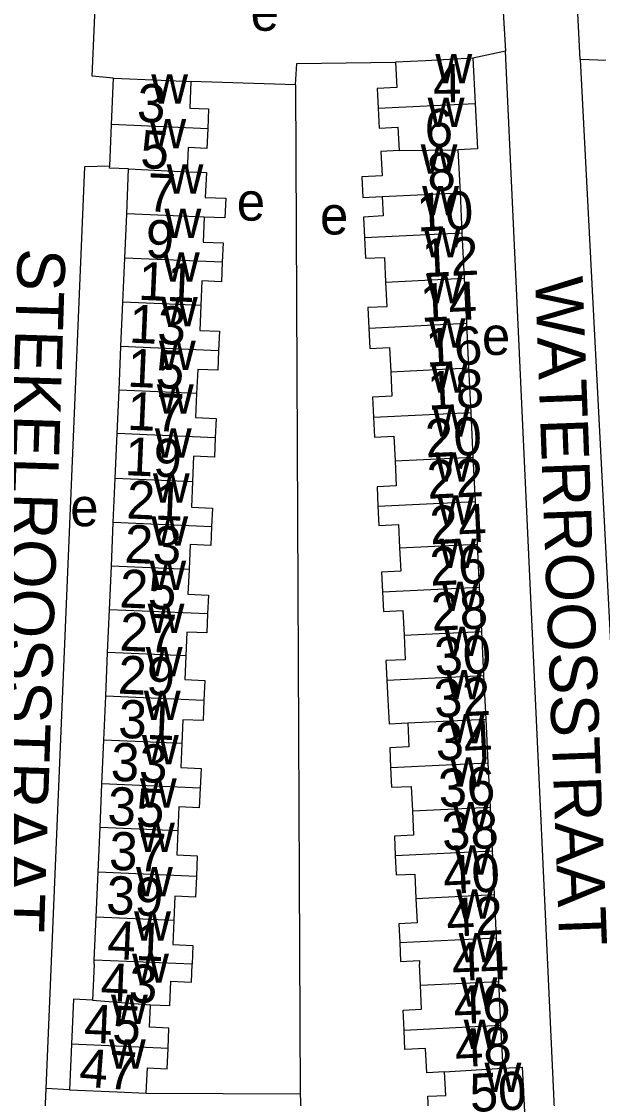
# Model space of a CAD drawing. Extents: x 161258 to 163262, y 380749 to 382054.
# Drawn here: x 162343 to 162403.5, y 380985.9 to 381098.8 of the extents above; entities that cross this region are included whole.
import ezdxf

# ---------------------------------------------------------------- set-up
doc = ezdxf.new("R2010")
doc.units = 0
for name, color, linetype in [('BLT_Basislijn', 7, 'Continuous'), ('BLT_Bebouwing', 7, 'Continuous'), ('BLT_Centroide', 7, 'Continuous'), ('BLT_Huisnummer', 7, 'Continuous'), ('BLT_Huisnummer_ tussenligend', 7, 'Continuous'), ('BLT_Onderverdeling_panden', 7, 'Continuous'), ('BLT_Straatnaam', 7, 'Continuous')]:
    doc.layers.add(name, color=color, linetype=linetype)

msp = doc.modelspace()

# ---------------------------------------------------------------- linework, layer by layer
at = {"layer": 'BLT_Basislijn'}
for p, q in [((162393.75, 381095.73), (162390.32, 381094.99)), ((162399.1, 380980.19), (162393.75, 381095.73)), ((162404.35, 381094.76), (162401.58, 381094.88)), ((162371.7, 381092.21), (162360.74, 381092.54)), ((162371.7, 381092.21), (162372.2, 380986.41)), ((162348.01, 380986.84), (162345.51, 380986.99)), ((162356.06, 380986.49), (162372.2, 380986.41))]:
    msp.add_line(p, q, dxfattribs=at)
for points in [[(162401.58, 381094.88), (162400.52, 381115.65), (162445.14, 381123.93), (162447.27, 381105.8), (162447.33, 381105.24)], [(162352.63, 381092.9), (162350.38, 381093.13), (162351.31, 381113.86), (162392.57, 381115.24), (162393.75, 381095.73)], [(162371.7, 381092.21), (162371.85, 381094.43), (162382.21, 381094.59)], [(162401.58, 381094.88), (162407.53, 380979.88), (162407.53, 380979.65)], [(162352.23, 381083.67), (162349.58, 381083.6), (162345.51, 380986.99)], [(162345.51, 380986.99), (162344.65, 380966.65), (162398.15, 380960.51), (162398.46, 380960.83), (162399.56, 380970.74), (162399.1, 380980.19)], [(162372.2, 380986.41), (162372.39, 380982.25), (162385.46, 380979.84), (162387.83, 380979.4)]]:
    msp.add_lwpolyline(points, dxfattribs=at)
at = {"layer": 'BLT_Bebouwing'}
for p, q in [((162390.32, 381094.99), (162390.55, 381090.26)), ((162352.42, 381088.05), (162352.63, 381092.9)), ((162390.55, 381090.26), (162390.79, 381085.49)), ((162352.23, 381083.67), (162352.42, 381088.05)), ((162390.79, 381085.49), (162388.75, 381085.39)), ((162388.75, 381085.39), (162388.97, 381080.89)), ((162354.01, 381078.7), (162354.21, 381083.39)), ((162388.97, 381080.89), (162389.17, 381076.69)), ((162353.81, 381074.04), (162354.01, 381078.7)), ((162389.17, 381076.69), (162389.4, 381071.93)), ((162353.61, 381069.41), (162353.81, 381074.04)), ((162389.4, 381071.93), (162389.64, 381067.21)), ((162353.4, 381064.77), (162353.61, 381069.41)), ((162389.64, 381067.21), (162389.86, 381062.52)), ((162353.21, 381060.2), (162353.4, 381064.77)), ((162389.86, 381062.52), (162390.09, 381057.87)), ((162353.01, 381055.65), (162353.21, 381060.2)), ((162390.09, 381057.87), (162390.32, 381053.17)), ((162352.81, 381050.95), (162353.01, 381055.65)), ((162390.32, 381053.17), (162390.54, 381048.53)), ((162352.6, 381046.32), (162352.81, 381050.95)), ((162390.54, 381048.53), (162390.76, 381044.05)), ((162352.41, 381041.75), (162352.6, 381046.32)), ((162390.76, 381044.05), (162390.98, 381039.55)), ((162352.21, 381037.18), (162352.41, 381041.75)), ((162390.98, 381039.55), (162391.21, 381034.91)), ((162352.01, 381032.7), (162352.21, 381037.18)), ((162391.21, 381034.91), (162391.43, 381030.28)), ((162351.81, 381028.11), (162352.01, 381032.7)), ((162391.43, 381030.28), (162391.66, 381025.71)), ((162351.61, 381023.49), (162351.81, 381028.11)), ((162391.66, 381025.71), (162391.88, 381021.13)), ((162351.41, 381018.92), (162351.61, 381023.49)), ((162391.88, 381021.13), (162392.11, 381016.49)), ((162351.21, 381014.34), (162351.41, 381018.92)), ((162392.11, 381016.49), (162392.33, 381011.9)), ((162351.01, 381009.66), (162351.21, 381014.34)), ((162392.33, 381011.9), (162392.55, 381007.31)), ((162350.81, 381004.96), (162351.01, 381009.66)), ((162392.55, 381007.31), (162392.77, 381002.77)), ((162350.61, 381000.45), (162350.81, 381004.96)), ((162392.77, 381002.77), (162392.91, 381000)), ((162350.59, 381000), (162350.43, 380996.24)), ((162350.59, 381000), (162350.61, 381000.45)), ((162384.81, 380997.81), (162384.72, 381000.01)), ((162392.91, 381000), (162393, 380998.21)), ((162393, 380998.21), (162393.22, 380993.62)), ((162393.22, 380993.62), (162393.44, 380989.11)), ((162348.22, 380991.62), (162348.01, 380986.84))]:
    msp.add_line(p, q, dxfattribs=at)
for points in [[(162382.21, 381094.59), (162382.34, 381091.94), (162380.27, 381091.84), (162380.37, 381089.76)], [(162390.32, 381094.99), (162385.33, 381094.74), (162382.21, 381094.59)], [(162352.63, 381092.9), (162357.63, 381092.68), (162360.74, 381092.54)], [(162360.74, 381092.54), (162360.62, 381089.77), (162362.6, 381089.68), (162362.51, 381087.61)], [(162380.37, 381089.76), (162380.47, 381087.68), (162382.46, 381087.78), (162382.58, 381085.33)], [(162362.51, 381087.61), (162362.42, 381085.53), (162360.46, 381085.62), (162360.35, 381083.09)], [(162382.58, 381085.33), (162380.67, 381085.23), (162380.8, 381082.65), (162378.67, 381082.55), (162378.78, 381080.4), (162380.81, 381080.49)], [(162354.21, 381083.39), (162352.22, 381083.47), (162352.23, 381083.67)], [(162360.35, 381083.09), (162362.36, 381083.01), (162362.25, 381080.4), (162364.39, 381080.31), (162364.3, 381078.25), (162362.13, 381078.35)], [(162380.81, 381080.49), (162380.91, 381078.46), (162378.83, 381078.35), (162378.94, 381076.19)], [(162362.13, 381078.35), (162362.02, 381075.72), (162364.11, 381075.63), (162364.03, 381073.6)], [(162378.94, 381076.19), (162379.04, 381074.03), (162381.03, 381074.12), (162381.15, 381071.53)], [(162364.03, 381073.6), (162363.94, 381071.57), (162361.89, 381071.66), (162361.78, 381069.06)], [(162381.15, 381071.53), (162381.28, 381068.94), (162379.31, 381068.85), (162379.41, 381066.71)], [(162361.78, 381069.06), (162361.66, 381066.46), (162363.73, 381066.37), (162363.65, 381064.32)], [(162379.41, 381066.71), (162379.52, 381064.58), (162381.58, 381064.68), (162381.71, 381062.12)], [(162363.65, 381064.32), (162363.56, 381062.28), (162361.45, 381062.37), (162361.34, 381059.85)], [(162381.71, 381062.12), (162381.83, 381059.57), (162379.78, 381059.47), (162379.88, 381057.37)], [(162361.34, 381059.85), (162361.23, 381057.34), (162363.38, 381057.24), (162363.29, 381055.21)], [(162379.88, 381057.37), (162379.98, 381055.28), (162382.02, 381055.38), (162382.15, 381052.77)], [(162363.29, 381055.21), (162363.2, 381053.17), (162361.02, 381053.27), (162360.9, 381050.6)], [(162382.15, 381052.77), (162382.27, 381050.17), (162380.26, 381050.07), (162380.36, 381048.03)], [(162360.9, 381050.6), (162360.79, 381047.94), (162363, 381047.84), (162362.91, 381045.87)], [(162380.36, 381048.03), (162380.46, 381046), (162382.5, 381046.1), (162382.62, 381043.65)], [(162362.91, 381045.87), (162362.83, 381043.91), (162360.66, 381044), (162360.55, 381041.4)], [(162382.62, 381043.65), (162382.74, 381041.21), (162380.73, 381041.11), (162380.83, 381039.05)], [(162360.55, 381041.4), (162360.43, 381038.8), (162362.58, 381038.71), (162362.49, 381036.73)], [(162380.83, 381039.05), (162380.93, 381036.99), (162382.96, 381037.09), (162383.09, 381034.52)], [(162362.49, 381036.73), (162362.4, 381034.75), (162360.3, 381034.84), (162360.2, 381032.35)], [(162383.09, 381034.52), (162383.21, 381031.94), (162381.19, 381031.85), (162381.29, 381029.78)], [(162360.2, 381032.35), (162360.09, 381029.85), (162362.2, 381029.76), (162362.11, 381027.66)], [(162381.29, 381029.78), (162381.39, 381027.72), (162381.52, 381025.21), (162383.49, 381025.31)], [(162362.11, 381027.66), (162362.02, 381025.56), (162359.91, 381025.65), (162359.8, 381023.14)], [(162383.49, 381025.31), (162383.61, 381022.8), (162381.59, 381022.7), (162381.69, 381020.63)], [(162359.8, 381023.14), (162359.69, 381020.63), (162361.8, 381020.54), (162361.71, 381018.47)], [(162381.69, 381020.63), (162381.79, 381018.56), (162383.84, 381018.66), (162383.97, 381016.1)], [(162361.71, 381018.47), (162361.62, 381016.41), (162359.48, 381016.5), (162359.37, 381013.98)], [(162383.97, 381016.1), (162384.09, 381013.53), (162382.08, 381013.44), (162382.18, 381011.4)], [(162359.37, 381013.98), (162359.26, 381011.47), (162361.4, 381011.38), (162361.31, 381009.21)], [(162382.18, 381011.4), (162382.28, 381009.37), (162384.22, 381009.46), (162384.34, 381006.91)], [(162361.31, 381009.21), (162361.21, 381007.04), (162359.05, 381007.14), (162358.94, 381004.6)], [(162384.34, 381006.91), (162384.47, 381004.36), (162382.54, 381004.26), (162382.64, 381002.28)], [(162358.94, 381004.6), (162358.83, 381002.07), (162360.96, 381001.98), (162360.88, 381000)], [(162382.64, 381002.28), (162382.73, 381000.29), (162384.7, 381000.39), (162384.72, 381000.01)], [(162356.49, 380995.77), (162358.53, 380995.68), (162358.64, 380998.23), (162360.79, 380998.13), (162360.88, 381000)], [(162383.09, 380993.11), (162382.99, 380995.19), (162384.92, 380995.29), (162384.81, 380997.81)], [(162350.43, 380996.24), (162348.43, 380996.33), (162348.22, 380991.62)], [(162358.34, 380991.18), (162358.43, 380993.32), (162356.39, 380993.41), (162356.49, 380995.77)], [(162387.34, 380988.73), (162385.47, 380988.64), (162385.35, 380991.17), (162383.19, 380991.06), (162383.09, 380993.11)], [(162356.06, 380986.49), (162356.18, 380989.14), (162358.24, 380989.05), (162358.34, 380991.18)], [(162385.68, 380984.05), (162385.58, 380986.16), (162387.46, 380986.25), (162387.34, 380988.73)], [(162393.44, 380989.11), (162395.49, 380989.21), (162395.72, 380984.54)], [(162348.01, 380986.84), (162353.01, 380986.63), (162356.06, 380986.49)]]:
    msp.add_lwpolyline(points, dxfattribs=at)
at = {"layer": 'BLT_Onderverdeling_panden'}
for p, q in [((162380.37, 381089.76), (162390.55, 381090.26)), ((162362.51, 381087.61), (162352.42, 381088.05)), ((162382.58, 381085.33), (162388.75, 381085.39)), ((162354.21, 381083.39), (162360.35, 381083.09)), ((162380.81, 381080.49), (162388.97, 381080.89)), ((162362.13, 381078.35), (162354.01, 381078.7)), ((162378.94, 381076.19), (162389.17, 381076.69)), ((162364.03, 381073.6), (162353.81, 381074.04)), ((162381.15, 381071.53), (162389.4, 381071.93)), ((162361.78, 381069.06), (162353.61, 381069.41)), ((162379.41, 381066.71), (162389.64, 381067.21)), ((162363.65, 381064.32), (162353.4, 381064.77)), ((162381.71, 381062.12), (162389.86, 381062.52)), ((162361.34, 381059.85), (162353.21, 381060.2)), ((162379.88, 381057.37), (162390.09, 381057.87)), ((162363.29, 381055.21), (162353.01, 381055.65)), ((162382.15, 381052.77), (162390.32, 381053.17)), ((162360.9, 381050.6), (162352.81, 381050.95)), ((162380.36, 381048.03), (162390.54, 381048.53)), ((162362.91, 381045.87), (162352.6, 381046.32)), ((162382.62, 381043.65), (162390.76, 381044.05)), ((162360.55, 381041.4), (162352.41, 381041.75)), ((162380.83, 381039.05), (162390.98, 381039.55)), ((162362.49, 381036.73), (162352.21, 381037.18)), ((162383.09, 381034.52), (162391.21, 381034.91)), ((162360.2, 381032.35), (162352.01, 381032.7)), ((162381.29, 381029.78), (162391.43, 381030.28)), ((162362.11, 381027.66), (162351.81, 381028.11)), ((162383.49, 381025.31), (162391.66, 381025.71)), ((162359.8, 381023.14), (162351.61, 381023.49)), ((162381.69, 381020.63), (162391.88, 381021.13)), ((162361.71, 381018.47), (162351.41, 381018.92)), ((162383.97, 381016.1), (162392.11, 381016.49)), ((162359.37, 381013.98), (162351.21, 381014.34)), ((162382.18, 381011.4), (162392.33, 381011.9)), ((162361.31, 381009.21), (162351.01, 381009.66)), ((162384.34, 381006.91), (162392.55, 381007.31)), ((162358.94, 381004.6), (162350.81, 381004.96)), ((162382.64, 381002.28), (162392.77, 381002.77)), ((162360.88, 381000), (162350.61, 381000.45)), ((162384.81, 380997.81), (162393, 380998.21)), ((162350.43, 380996.24), (162356.49, 380995.77)), ((162383.09, 380993.11), (162393.22, 380993.62)), ((162358.34, 380991.18), (162348.22, 380991.62)), ((162387.34, 380988.73), (162393.44, 380989.11))]:
    msp.add_line(p, q, dxfattribs=at)

# ---------------------------------------------------------------- texts
at = {"layer": 'BLT_Centroide'}
for s, p in [('e', (162367, 381097.88)), ('w', (162386.38, 381092.38)), ('w', (162356.58, 381090.25)), ('w', (162385.57, 381087.78)), ('w', (162356.38, 381085.56)), ('w', (162384.83, 381082.91)), ('w', (162358.19, 381080.81)), ('e', (162365.55, 381077.97)), ('w', (162384.99, 381078.53)), ('e', (162374.28, 381076.52)), ('w', (162357.97, 381076.16)), ('w', (162385.16, 381074.12)), ('w', (162357.8, 381071.56)), ('w', (162385.4, 381069.31)), ('w', (162357.59, 381066.88)), ('w', (162385.67, 381064.66)), ('e', (162391.26, 381063.89)), ('w', (162357.38, 381062.31)), ('w', (162385.9, 381059.94)), ('w', (162357.17, 381057.72)), ('w', (162386.12, 381055.31)), ('w', (162356.96, 381053.12)), ('w', (162386.34, 381050.59)), ('w', (162356.75, 381048.41)), ('e', (162348.08, 381045.93)), ('w', (162386.58, 381046.09)), ('w', (162356.58, 381043.88)), ('w', (162386.8, 381041.56)), ('w', (162356.38, 381039.25)), ('w', (162387.04, 381037.03)), ('w', (162356.2, 381034.75)), ('w', (162387.26, 381032.34)), ('w', (162356, 381030.19)), ('w', (162387.46, 381027.78)), ('w', (162355.8, 381025.62)), ('w', (162387.69, 381023.16)), ('w', (162355.6, 381020.97)), ('w', (162387.92, 381018.62)), ('w', (162355.39, 381016.44)), ('w', (162388.16, 381013.94)), ('w', (162355.19, 381011.78)), ('w', (162388.34, 381009.41)), ('w', (162354.98, 381007.12)), ('w', (162388.56, 381004.78)), ('w', (162354.78, 381002.47)), ('w', (162388.81, 381000.22)), ('w', (162354.57, 380998.06)), ('w', (162389.02, 380995.56)), ('w', (162352.36, 380993.75)), ('w', (162389.35, 380991.12)), ('w', (162352.14, 380989.06)), ('w', (162391.53, 380986.62))]:
    msp.add_text(s, height=4, dxfattribs=at).set_placement(p)
at = {"layer": 'BLT_Huisnummer'}
for s, rotation, p in [('4', 0.5761, (162386.15, 381090.36)), ('3', 357.2648, (162355.03, 381088.35)), ('8', 2.7912, (162385.61, 381081.02)), ('7', 357.5119, (162356.08, 381078.95)), ('12', 2.7941, (162385.07, 381072.03)), ('11', 357.5061, (162355.17, 381069.68)), ('16', 2.7922, (162385.44, 381062.65)), ('15', 357.5095, (162354.02, 381060.57)), ('20', 2.7809, (162385.4, 381053.14)), ('19', 357.5119, (162353.76, 381051.29)), ('24', 2.7906, (162385.88, 381044.03)), ('23', 357.5054, (162353.72, 381042.12)), ('28', 2.791, (162386.03, 381034.95)), ('27', 357.5089, (162353.21, 381032.9)), ('32', 2.792, (162386.31, 381025.86)), ('31', 357.5104, (162353.07, 381023.76)), ('36', 2.7893, (162386.79, 381016.45)), ('35', 357.5027, (162351.94, 381014.62)), ('40', 2.7956, (162387.29, 381007.36)), ('39', 357.5119, (162351.81, 381005.29)), ('44', 2.226, (162388.19, 380998.24)), ('43', 357.5027, (162351.21, 380996.17)), ('48', 2.789, (162388.51, 380989.2)), ('47', 355.5839, (162348.94, 380987.22))]:
    msp.add_text(s, height=4, rotation=rotation, dxfattribs=at).set_placement(p)
at = {"layer": 'BLT_Huisnummer_ tussenligend'}
for s, rotation, p in [('6', 0.5761, (162385.28, 381085.67)), ('5', 357.2648, (162355.38, 381083.49)), ('10', 2.7912, (162384.5, 381076.81)), ('9', 357.5119, (162355.92, 381074.09)), ('14', 2.7941, (162384.88, 381067.34)), ('13', 357.5061, (162354.2, 381065.19)), ('18', 2.7922, (162385.62, 381058.14)), ('17', 357.5095, (162354, 381056.05)), ('22', 2.7809, (162385.58, 381048.8)), ('21', 357.5119, (162353.93, 381046.76)), ('26', 2.7906, (162385.88, 381039.69)), ('25', 357.5054, (162353.2, 381037.43)), ('30', 2.791, (162386.37, 381030.26)), ('29', 357.5089, (162353.04, 381028.39)), ('34', 2.792, (162386.47, 381021.34)), ('33', 357.5104, (162352.28, 381019.26)), ('38', 2.7893, (162387.15, 381011.93)), ('37', 357.5027, (162352.1, 381009.93)), ('42', 2.7956, (162387.62, 381002.88)), ('41', 357.5119, (162351.91, 381000.58)), ('46', 2.226, (162388.36, 380993.73)), ('45', 357.5027, (162349.47, 380991.82)), ('50', 2.789, (162390.07, 380984.51))]:
    msp.add_text(s, height=4, rotation=rotation, dxfattribs=at).set_placement(p)
at = {"layer": 'BLT_Straatnaam'}
for s, rotation, p in [('STEKELROOSSTRAAT', 268.2038, (162342.6, 381075.12)), ('WATERROOSSTRAAT', 272.0905, (162396.83, 381072.03))]:
    msp.add_text(s, height=5, rotation=rotation, dxfattribs=at).set_placement(p)

doc.saveas('drawing.dxf')
